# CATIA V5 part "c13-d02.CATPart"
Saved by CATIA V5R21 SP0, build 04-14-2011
Part number: Part1
Bounding box of the stored display mesh (mm): x -33 to 33, y -200.819 to 48, z -35 to 35
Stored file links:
  D:\CATIA V5R21 E-RESOURCES\CATIA-V5R21\catia-v5r21-prt\c13-catia-v5r20-prt\c13-catia-v5r20-figr-13-10\cat_v5r21_c13-d02.CATPart
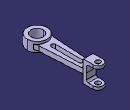
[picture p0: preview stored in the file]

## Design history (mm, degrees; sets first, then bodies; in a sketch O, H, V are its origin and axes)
Body1 (main body)
  Sketch1 on yz-plane, origin (0, 0, 0), H (0, 1, 0), V (0, 0, 1)
    line L1 (0, 0) -> (0, -35)
    point P1 (0, -35)
    line L2 (0, -35) -> (48, -35)
    point P2 (48, -35)
    line L3 (48, -35) -> (48, -25)
    point P3 (48, -25)
    line L4 (48, -25) -> (10, -25)
    point P4 (10, -25)
    line L5 (10, -25) -> (10, 0)
    point P5 (10, 0)
    point P6 (0, 0)
    point P7 (0, 0)
    point P8 (0, 35)
    point P9 (48, 35)
    point P10 (48, 25)
    point P11 (10, 25)
    point P12 (10, 0)
    point P13 (0, 0)
    line L6 (0, 0) -> (0, 35)
    line L7 (0, 35) -> (48, 35)
    line L8 (48, 35) -> (48, 25)
    line L9 (48, 25) -> (10, 25)
    line L10 (10, 25) -> (10, 0)
    length L8 = 10
    distance P3 L9 = 50
    length L2 = 48
    distance L10 L6 = 10
    vertical: L1 V, L3 V, L5 V
    horizontal: L2 H, L4 H
    symmetry: O P7 H, P1 P8 H, P2 P9 H, P3 P10 H, P4 P11 H, P5 P12 H, P6 P13 H, L1 L6 H, L2 L7 H, L3 L8 H, L4 L9 H, L5 L10 H
    coincidence: P13 P7, P12 P5, P6 P7
  Pad1: profile Sketch1, direction (1, 0, 0), length 16, mirrored extent
  Sketch2 on xy-plane, origin (0, 0, 0), H (1, 0, 0), V (0, 1, 0)
    circle A1 centre (0, -168) radius 33
    point P1 (0, -168)
    circle A2 centre (0, -168) radius 20
    distance P1 H = 168
    radius A1 = 33
    radius A2 = 20
    coincidence: P1 V
  Pad2: profile Sketch2, direction (0, 0, 1), length 16, mirrored extent
  Sketch3 on xy-plane, origin (0, 0, 0), H (1, 0, 0), V (0, 1, 0)
    line L1 (-16, 0) -> (-25, -146.4593)
    point P1 (-16, 0)
    point P2 (-25, -146.4593)
    line L2 (16, 0) -> (25, -146.4593)
    point P3 (16, 0)
    point P4 (25, -146.4593)
    reference projected line E1 (16, 48) -> (16, 0) from edge [face of Pad1 | face of Pad1]
    reference projected line E2 (-16, 48) -> (-16, 0) from edge [face of Pad1 | face of Pad1]
    projected circle E3 centre (0, -168) radius 33 from edge [face of Pad2 | face of Pad2]
    projected arc E4 centre (0, -168) radius 33 from (25, -146.4593) to (-25, -146.4593) ccw from edge [face of Pad2 | face of Pad2]
    line L3 (-16, 0) -> (16, 0)
    distance P4 P2 H = 50
    coincidence: P1 H, P3 H, P3 E1, P1 E2, P2 E3, P4 E3
    symmetry: P4 P2 V
    horizontal: L3 H
  Pad3: profile Sketch3, direction (0, 0, 1), length 8, mirrored extent
  Fillet1: radius 6, on edge [face of Pad1 | face of Pad3]; edge [face of Pad3 | face of Pad1]; edge [face of Pad1 | face of Pad1] (x2)
  Fillet2: radius 30, on edge [face of Pad3 | face of Pad2]; edge [face of Pad2 | face of Pad3]
  TritangentFillet1: Face1 face of Pad1, Face2 face of Pad1, RemoveFace face of Pad1
  TritangentFillet2: Face1 face of Pad1, Face2 face of Pad1, RemoveFace face of Pad1
  Sketch4 on face of Pad1, origin (2.8418, 32, 35), H (1, 0, 0), V (0, 1, 0)
    point P1 (-2.8418, 0)
    reference projected arc E1 centre (-2.8418, 0) radius 16 from (13.1582, 0) to (-18.8418, 0) ccw from edge [face of Pad1 | face of TritangentFillet1]
    concentricity: P1 E1
  Hole1: placed by Sketch4, at (0, 32, 35) direction (0, 0, -1), diameter 16, through (limit type 3)
  Sketch5 on face of Pad3, origin (0, 0, 8), H (1, 0, 0), V (0, 1, 0)
    construction line L1 (0, -25) -> (0, -115)
    point P1 (0, -25)
    line L2 (7, -25) -> (7, -115)
    line L3 (-7, -115) -> (-7, -25)
    arc A1 centre (0, -115) radius 7 from (7, -115) to (-7, -115) cw
    arc A2 centre (0, -25) radius 7 from (-7, -25) to (7, -25) cw
    distance P1 H = 25
    length L1 = 90
    radius A1 = 7
    coincidence: P1 V
    vertical: L1 V
    tangency: A1 L2, A2 L2, A1 L3, A2 L3
    parallelism: L1 L2
  Pocket1: profile Sketch5, direction (0, 0, -1), through (limit type 3)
